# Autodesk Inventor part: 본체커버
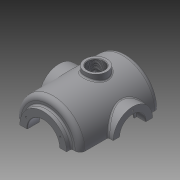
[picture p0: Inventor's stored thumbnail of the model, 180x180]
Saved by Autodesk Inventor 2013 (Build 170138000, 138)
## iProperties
Created: 2016-02
Part Number: 본체커버
Material: 알루미늄 6061
Document SubType Name: Modeling
Designer: mduedu
Density: 2.71 g/cm^3
Mass: 1187.09 g
Surface Area: 904.866 cm^2
Volume: 438.041 cm^3
Author: mduedu
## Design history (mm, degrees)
sketch "스케치2"
  geometry: L1 (0, 90)-(0, -90); L2 (65, -65.993)-(65, 90); L3 (65, 90)-(0, 90); A1 r 100 centre (0, 10) between (0, -90) and (65, -65.993); 2 further points
  constraints: 6 end point, 2 point on circle, 1 centre point, 1 coincident, 1 horizontal, 1 midpoint, 1 parallel, 1 point on line, 1 vertical
  dimensions: "d3" = 180 distance of L1.start L1.end; "d5" = 130 diameter of L2 L1; "d6" = 100 radius of A1
revolve "회전1" sketch "스케치2" stored, may be unused: angle "d7" = 90 deg
sketch "스케치3"
  geometry: C1 r 47.5 at (0, 0); 1 further point
  constraints: 1 centre point, 1 coincident
  dimensions: "d8" = 95 diameter of C1
extrude "돌출2" join sketch "스케치3" distance "d10" = 10; taper "d11" = 0 deg
sketch "스케치5"
  geometry: L1 (47.5, 100)-(47.5, 90) reference; L2 (47.5, 90)-(65, 90) reference; L3 (65, 90)-(65, -65.993) reference; L4 (-65, -65.993)-(-65, 90) reference; L5 (-65, 90)-(-47.5, 90) reference; L6 (-47.5, 90)-(-47.5, 100) reference; L7 (-47.5, 100)-(47.5, 100) reference; L8 (55, 75)-(55, -61.239); L9 (0, 75)-(55, 75); L10 (0, 75)-(0, -80); A1 r 100 centre (0, 10) between (-65, -65.993) and (0, -90) reference; A2 r 100 centre (0, 10) between (0, -90) and (65, -65.993) reference; A3 r 90 centre (0, 10) between (0, -80) and (55, -61.239); 1 further point
  constraints: 6 end point, 2 point on circle, 1 centre point, 1 parallel, 1 perpendicular, 1 point on line, 1 vertical
  dimensions: "d13" = 10 distance between parallel lines of L3 L8; "d14" = 10 radial gap between concentric circles of A3 A1; "d15" = 15 distance between parallel lines of L9 L2
revolve "회전2" sketch "스케치5" stored, may be unused: angle "d16" = 90 deg
hole "구멍1" diameter "d19" = 65; stored, may be unused: countersink angle "d23" = 90 deg, drill point angle "d25" = 118 deg; dims "d17" = 10, "d18" = 10, "d20" = 6, "d21" = 4, "d22" = 2, "d24" = 8
node "작업 평면1"
sketch "스케치6"
  geometry: L1 (47.5, 100)-(-47.5, 100) reference; C1 r 40 at (0, -7); 1 further point
  constraints: 1 centre point, 1 vertical alignment
  dimensions: "d27" = 80 diameter of C1; "d29" = 107 distance from line of C1.centre L1
extrude "돌출3" join sketch "스케치6" stored distance "d30" = 10; taper "d31" = 0 deg
hole "구멍2" diameter "d34" = 42; stored, may be unused: countersink angle "d38" = 90 deg, drill point angle "d40" = 118 deg; dims "d32" = 10, "d33" = 10, "d35" = 6, "d36" = 52, "d37" = 18, "d39" = 8
sketch "스케치7" dims "d41" = 65
  geometry: C1 r 40 at (0, 0) reference; 3 further points
  constraints: 2 vertical alignment, 1 coincident, 2 other
hole "구멍3" sketch "스케치7" at (0, 32.5) diameter "d43" = 3.242; stored, may be unused: countersink angle "d47" = 90 deg, drill point angle "d49" = 118 deg; dims "d44" = 11, "d45" = 13, "d46" = 18, "d48" = 13
sketch "스케치8" dims "d53" = 80
  geometry: 3 further points
  constraints: 2 vertical alignment, 1 coincident, 2 other
hole "구멍4" sketch "스케치8" at (0, -40) diameter "d56" = 3.242; stored, may be unused: countersink angle "d60" = 90 deg, drill point angle "d62" = 118 deg; dims "d57" = 11, "d58" = 13, "d59" = 18, "d61" = 13
fillet "모깎기1" dims "d66" = 10
fillet "모깎기2" dims "d67" = 3
fillet "모깎기3" dims "d68" = 0.3
chamfer "모따기1" distance "d69" = 1; stored, may be unused: second distance "d70" = 2, angle "d71" = 45 deg
node "작업 평면5"
sketch "스케치10"
  geometry: L1 (-50, 66)-(50, 66); L2 (50, 66)-(50, 50); L3 (50, 50)-(-50, 50); L4 (-50, 50)-(-50, 66); 2 further points
  constraints: 8 end point, 2 horizontal, 2 vertical, 1 midpoint, 1 vertical alignment
  dimensions: "d177" = 50 distance from line of L3 point (0, 0); "d178" = 100 distance of L1.start L1.end; "d179" = 16 distance of L3.end L1.start
extrude "돌출5" join sketch "스케치10" stored distance "d84" = 10; taper "d85" = 0 deg
sketch "스케치21" dims "d180" = 220, "d182" = 130
  geometry: L1 (65, 58)-(-65, 58); L2 (-65, 58)-(-65, -32); L3 (-65, -32)-(65, -32); L4 (65, -32)-(65, 58); L5 (50, 50)-(50, 66) reference; 4 further points
  constraints: 8 end point, 3 horizontal alignment, 3 midpoint, 2 parallel, 1 horizontal, 1 perpendicular, 1 vertical alignment, 4 other
extrude "돌출13" join sketch "스케치21" distance "d183" = 10; taper "d184" = 0 deg
sketch "스케치11"
  geometry: L1 (-65, 80)-(-65, -61.239) reference; L2 (-100, -97)-(-100, -32) reference; L3 (-65, -42.793)-(-100, -63); L4 (-100, -97)-(-110, -97) reference; 1 further point
  constraints: 2 end point, 2 point on line
  dimensions: "d185" = 34 distance from line of L3.end L4; "d186" = 120 deg angle of L2 L3
feature "리브1" sketch "스케치11" dims "d88" = 1, "d89" = 16, "d90" = 0, "d91" = 0, "d92" = 1, "d93" = 1
fillet "모깎기12"
fillet "모깎기13"
fillet "모깎기16" dims "d167" = 3
fillet "모깎기18"
fillet "모깎기17" dims "d168" = 3
fillet "모깎기19" dims "d187" = 3
node "작업 평면6"
sketch "스케치19"
  geometry: L1 (75, -47)-(75, 33) reference; L2 (-75, -47)-(-75, 33) reference; L3 (75, -7)-(-75, -7); C1 r 22.5 at (0, -7); 1 further point
  constraints: 3 midpoint, 2 end point, 1 centre point
  dimensions: "d149" = 45 diameter of C1
extrude "돌출11" join sketch "스케치19" stored distance "d150" = 10; taper "d151" = 0 deg
hole "구멍6" diameter "d154" = 33.376; stored, may be unused: countersink angle "d158" = 90 deg, drill point angle "d160" = 118 deg; dims "d155" = 6, "d156" = 4, "d157" = 2, "d159" = 8, "d190" = 10, "d191" = 10
fillet "모깎기11" dims "d161" = 3
chamfer "모따기3" distance "d164" = 1; stored, may be unused: second distance "d165" = 2, angle "d166" = 45 deg
sketch "스케치22" dims "d189" = 20
  geometry: L1 (-10, -123)-(10, -123); L2 (10, -123)-(10, -103); L3 (10, -103)-(-10, -103); L4 (-10, -103)-(-10, -123); A1 r 65 centre (0, -58) between (-65, -58) and (65, -58) reference; 2 further points
  constraints: 8 end point, 2 parallel, 1 horizontal, 1 horizontal alignment, 1 midpoint, 1 perpendicular, 1 tangent, 1 vertical alignment, 2 other
  dimensions: "d193" = 30 dimension on L1
extrude "돌출14" cut sketch "스케치22" stored distance "d194" = 10; taper "d195" = 0 deg
fillet "모깎기21" dims "d196" = 3
feature "분할1"
node "솔리드2"
pattern_circular "원형 패턴1" dims angle "d51" = 360 deg
mirror "대칭1"
pattern_circular "원형 패턴2" dims angle "d64" = 360 deg
node "절단 모서리 투영1"
other parameters: "d26" = 75, "d136" = 175
